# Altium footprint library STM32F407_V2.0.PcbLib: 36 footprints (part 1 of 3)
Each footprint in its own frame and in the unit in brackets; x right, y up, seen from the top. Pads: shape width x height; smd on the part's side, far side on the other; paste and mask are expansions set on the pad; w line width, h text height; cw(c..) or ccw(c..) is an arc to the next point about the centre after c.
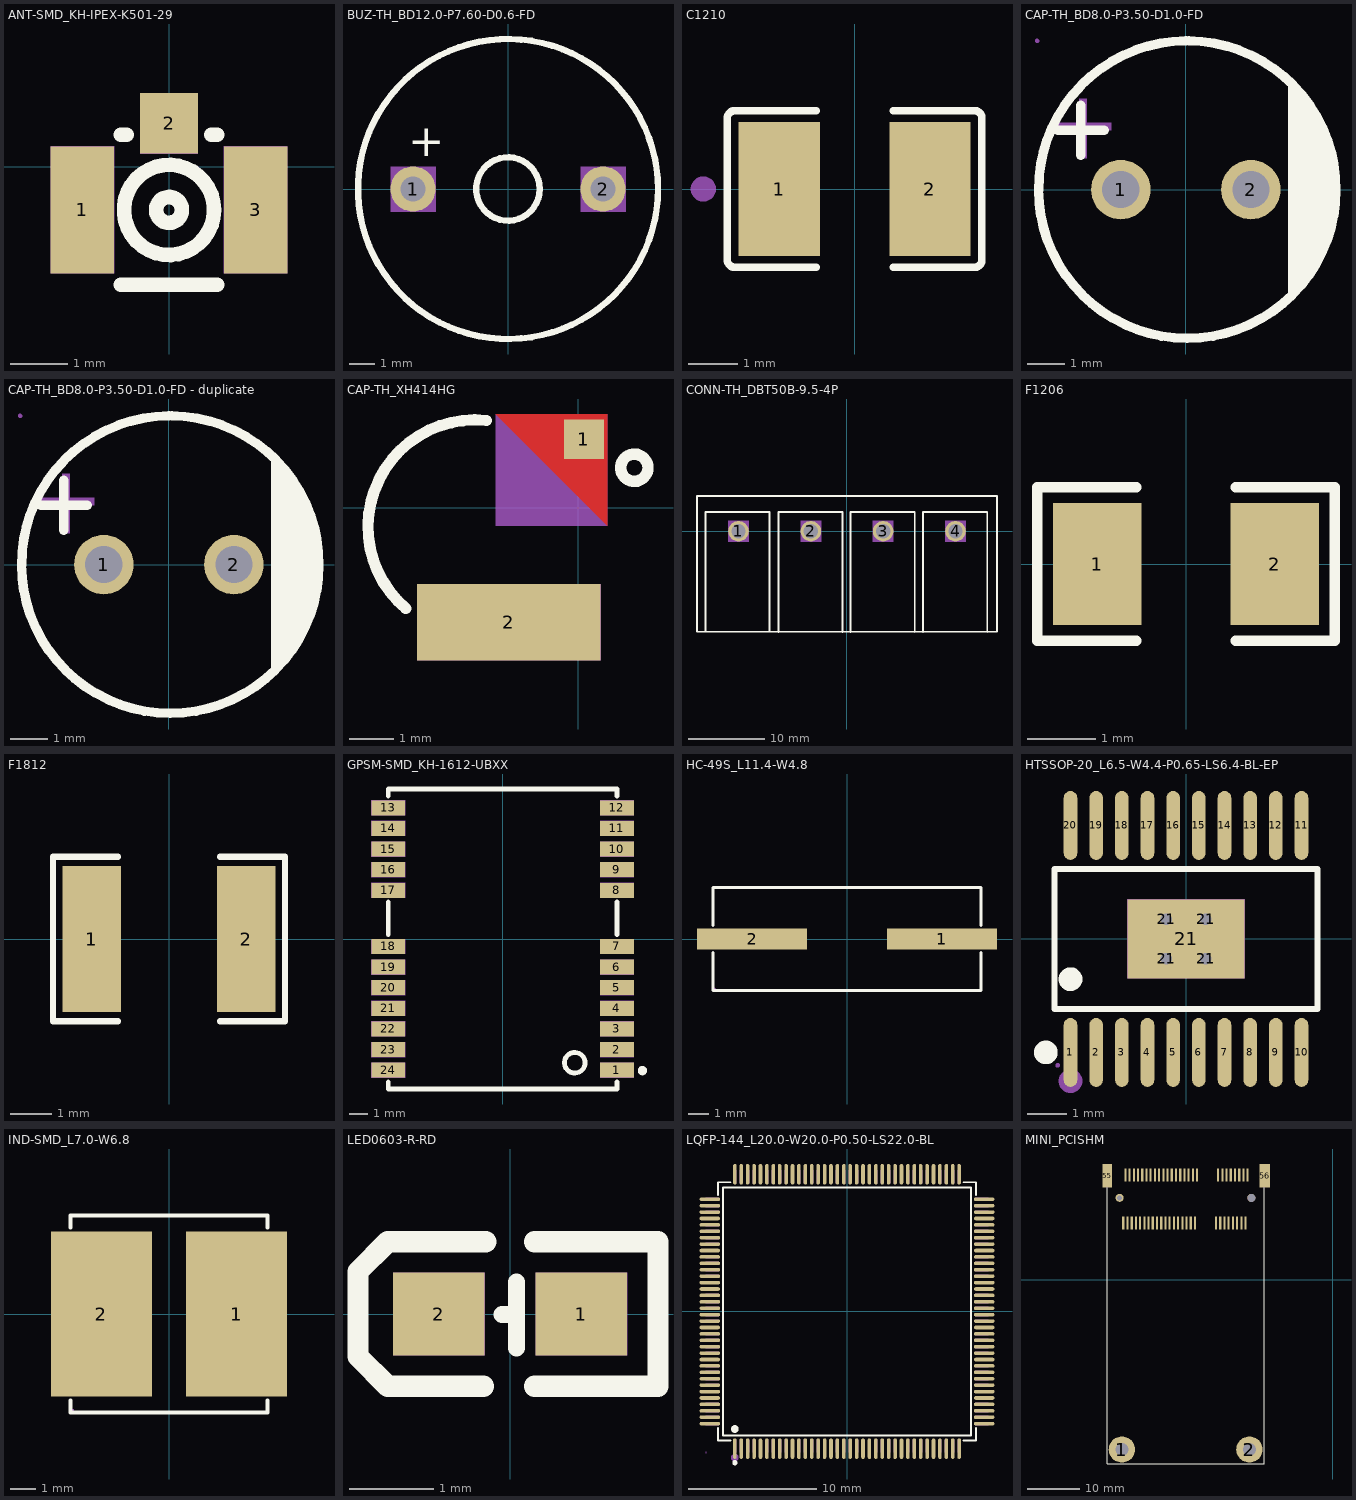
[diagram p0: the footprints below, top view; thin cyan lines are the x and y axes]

## ANT-SMD_KH-IPEX-K501-29 [mm]
pads (3):
  rect 1.1x2.2 smd: 1(-1.5,-0.75) 3(1.5,-0.75)
  rect 1x1.05 smd: 2(0,0.75)
Top Overlay:
  circle w0.254: c0,-0.75 r0.224
  circle w0.254: c0,-0.75 r0.781
  lines w0.254: -0.837,-2.05 0.837,-2.05 ; -0.837,0.55 -0.731,0.55 ; 0.731,0.55 0.837,0.55
Mechanical 5:
  region: 0.95,0.35 2.05,0.35 2.05,-1.85 0.95,-1.85
  region: -0.5,1.275 0.5,1.275 0.5,0.225 -0.5,0.225
  region: -2.05,0.35 -0.95,0.35 -0.95,-1.85 -2.05,-1.85

## BUZ-TH_BD12.0-P7.60-D0.6-FD [mm]
pads (2):
  round 1.8 hole 1: 1(-3.8,0) 2(3.8,0)
Top Overlay:
  circle w0.254: c0,0 r1.27
  circle w0.254: c0,0 r6
  text "+" at -3.996,1.316 h1.27
Mechanical 5:
  region: 2.9,0.9 4.7,0.9 4.7,-0.9 2.9,-0.9
  region: -4.7,0.9 -2.9,0.9 -2.9,-0.9 -4.7,-0.9

## C1210 [mm]
pads (2):
  rect 1.635x2.7 smd: 1(-1.517,0) 2(1.517,0)
Top Overlay:
  lines w0.152: -0.776,-1.579 -2.411,-1.579 cw(c-2.411,-1.426) -2.564,-1.426 -2.564,1.426 cw(c-2.411,1.426) -2.411,1.579 -0.776,1.579 ; 0.776,-1.579 2.411,-1.579 ccw(c2.411,-1.426) 2.564,-1.426 2.564,1.426 ccw(c2.411,1.426) 2.411,1.579 0.776,1.579
Top Paste:
  region: 0.7,-1.25 0.7,-0.559 0.8,-0.459 1.156,-0.459 1.256,-0.359 1.256,0.359 1.156,0.459 0.8,0.459 0.7,0.559 0.7,1.25 0.8,1.35 2.235,1.35 2.335,1.25 2.335,-1.25 2.235,-1.35 0.8,-1.35
  region: -0.7,-1.25 -0.7,-0.559 -0.8,-0.459 -1.156,-0.459 -1.256,-0.359 -1.256,0.359 -1.156,0.459 -0.8,0.459 -0.7,0.559 -0.7,1.25 -0.8,1.35 -2.235,1.35 -2.335,1.25 -2.335,-1.25 -2.235,-1.35 -0.8,-1.35
Mechanical 5:
  region: -1.6,-1.25 -1.6,1.25 -1,1.25 -1,-1.25
  region: 1.6,-1.25 1.6,1.25 1,1.25 1,-1.25
Mechanical 6:
  circle w0.06: c-1.6,-1.25 r0.03
Mechanical 15:
  circle w0.254: c-3.048,0 r0.127

## CAP-TH_BD8.0-P3.50-D1.0-FD [mm]
pads (2):
  round 1.6 hole 1: 1(-1.75,0) 2(1.75,0)
Top Overlay:
  region: 2.75,-3 2.941,-2.8 3.268,-2.355 3.536,-1.872 3.741,-1.359 3.88,-0.824 3.95,-0.276 3.95,0.276 3.88,0.824 3.741,1.359 3.536,1.872 3.268,2.355 2.941,2.8 2.75,3
  lines w0.254: -3.445,1.6 -2.2,1.6 ; -2.822,0.927 -2.822,2.273 ; 0.003,4 ccw(c0.038,0.001) 0.074,4
Mechanical 5:
  circle w0.3: c-1.75,0 r0.15
  circle w0.3: c1.75,0 r0.15
Mechanical 6:
  circle w0.06: c-4,4 r0.03
Mechanical 15:
  region: -2.865,0.845 -2.865,2.445 -2.665,2.445 -2.665,0.845
  region: -3.6,1.8 -2,1.8 -2,1.6 -3.6,1.6

## CAP-TH_BD8.0-P3.50-D1.0-FD - duplicate [mm]
pads (2):
  round 1.6 hole 1: 1(-1.75,0) 2(1.75,0)
Top Overlay:
  region: 2.75,-3 2.941,-2.8 3.268,-2.355 3.536,-1.872 3.741,-1.359 3.88,-0.824 3.95,-0.276 3.95,0.276 3.88,0.824 3.741,1.359 3.536,1.872 3.268,2.355 2.941,2.8 2.75,3
  lines w0.254: -3.445,1.6 -2.2,1.6 ; -2.822,0.927 -2.822,2.273 ; 0.003,4 ccw(c0.038,0.001) 0.074,4
Mechanical 5:
  circle w0.3: c-1.75,0 r0.15
  circle w0.3: c1.75,0 r0.15
Mechanical 6:
  circle w0.06: c-4,4 r0.03
Mechanical 15:
  region: -2.865,0.845 -2.865,2.445 -2.665,2.445 -2.665,0.845
  region: -3.6,1.8 -2,1.8 -2,1.6 -3.6,1.6

## CAP-TH_XH414HG [mil]
pads (3):
  round 0 smd: 1(-23.48,57.63)
  rect 35x35 smd: 1(5,60)
  rect 161.4x66.93 smd: 2(-60.88,-100.83)
Top Layer:
  region: -72.69,82.24 25.74,82.24 25.74,-16.19
Top Overlay:
  circle w10: c49.36,34.99 r12
  lines w10: -151.56,-88.79 cw(c-90.63,-17.05) -80.7,76.56
Top Paste:
  region: -72.69,82.24 25.74,82.24 25.74,-16.19
Top Solder:
  region: -72.69,82.24 25.74,82.24 25.74,-16.19
Mechanical 5:
  region: -72.69,82.24 25.74,82.24 25.74,-16.19 -72.69,-16.19
  region: -141.58,-67.37 19.82,-67.37 19.82,-134.3 -141.58,-134.3
Mechanical 15:
  lines w0.1: -62.82,-8.75 -60.82,-6.75

## CONN-TH_DBT50B-9.5-4P [mm]
pads (4):
  round 2.7 hole 1.9: 1(-14.25,0) 2(-4.75,0) 3(4.75,0) 4(14.25,0)
Top Overlay:
  lines w0.254: -18.595,-13.2 -18.595,2.54 -10.159,2.54 -10.159,-13.2 ; -9.016,-13.208 -9.016,2.532 -0.58,2.532 -0.58,-13.208 ; 0.458,-13.208 0.458,2.532 8.894,2.532 8.894,-13.208 ; 9.983,-13.208 9.983,2.532 18.419,2.532 18.419,-13.208 ; -19.7,-13.2 19.7,-13.2 19.7,4.6 -19.7,4.6 -19.7,-13.2
Mechanical 5:
  region: 12.9,1.35 15.6,1.35 15.6,-1.35 12.9,-1.35
  region: 3.4,1.35 6.1,1.35 6.1,-1.35 3.4,-1.35
  region: -6.1,1.35 -3.4,1.35 -3.4,-1.35 -6.1,-1.35
  region: -15.6,1.35 -12.9,1.35 -12.9,-1.35 -15.6,-1.35

## F1206 [mm]
pads (2):
  rect 1.293x1.782 smd: 1(-1.296,0) 2(1.296,0)
Top Overlay:
  lines w0.152: -0.726,-1.12 -2.172,-1.12 -2.172,1.12 -0.726,1.12 ; 0.726,-1.12 2.172,-1.12 2.172,1.12 0.726,1.12
Top Paste:
  region: -0.65,-0.791 -0.65,-0.403 -0.75,-0.303 -0.99,-0.303 -1.09,-0.203 -1.09,0.203 -0.99,0.303 -0.75,0.303 -0.65,0.403 -0.65,0.791 -0.75,0.891 -1.843,0.891 -1.943,0.791 -1.943,-0.791 -1.843,-0.891 -0.75,-0.891
  region: 0.65,-0.791 0.65,-0.403 0.75,-0.303 0.99,-0.303 1.09,-0.203 1.09,0.203 0.99,0.303 0.75,0.303 0.65,0.403 0.65,0.791 0.75,0.891 1.843,0.891 1.943,0.791 1.943,-0.791 1.843,-0.891 0.75,-0.891
Mechanical 5:
  region: 1.625,-0.825 1.625,0.825 0.975,0.825 0.975,-0.825
  region: -1.625,-0.825 -1.625,0.825 -0.975,0.825 -0.975,-0.825
Mechanical 6:
  circle w0.06: c-1.625,-0.825 r0.03

## F1812 [mm]
pads (2):
  rect 1.407x3.499 smd: 1(-1.853,0) 2(1.853,0)
Top Overlay:
  lines w0.152: -1.226,-1.978 -2.785,-1.978 -2.785,1.978 -1.226,1.978 ; 1.226,-1.978 2.785,-1.978 2.785,1.978 1.226,1.978
Top Paste:
  region: -1.15,-1.65 -1.15,-0.695 -1.25,-0.595 -1.528,-0.595 -1.628,-0.495 -1.628,0.495 -1.528,0.595 -1.25,0.595 -1.15,0.695 -1.15,1.65 -1.25,1.75 -2.457,1.75 -2.557,1.65 -2.557,-1.65 -2.457,-1.75 -1.25,-1.75
  region: 1.15,-1.65 1.15,-0.695 1.25,-0.595 1.528,-0.595 1.628,-0.495 1.628,0.495 1.528,0.595 1.25,0.595 1.15,0.695 1.15,1.65 1.25,1.75 2.457,1.75 2.557,1.65 2.557,-1.65 2.457,-1.75 1.25,-1.75
Mechanical 5:
  region: 2.275,-1.62 2.275,1.62 1.525,1.62 1.525,-1.62
  region: -2.275,-1.62 -2.275,1.62 -1.525,1.62 -1.525,-1.62
Mechanical 6:
  circle w0.06: c-2.275,-1.62 r0.03

## GPSM-SMD_KH-1612-UBXX [mm]
pads (24):
  rect 1.8x0.8 smd: 1(6.1,-7) 2(6.1,-5.9) 3(6.1,-4.8) 4(6.1,-3.7) 5(6.1,-2.6) 6(6.1,-1.5) 7(6.1,-0.4) 8(6.1,2.6) 9(6.1,3.7) 10(6.1,4.8) 11(6.1,5.9) 12(6.1,7) 13(-6.1,7) 14(-6.1,5.9) 15(-6.1,4.8) 16(-6.1,3.7) 17(-6.1,2.6) 18(-6.1,-0.4) 19(-6.1,-1.5) 20(-6.1,-2.6) 21(-6.1,-3.7) 22(-6.1,-4.8) 23(-6.1,-5.9) 24(-6.1,-7)
Top Overlay:
  circle w0.254: c3.85,-6.6 r0.55
  circle w0.254: c7.46,-7.02 r0.12
  lines w0.254: -6.1,-7.631 -6.1,-8 6.1,-8 6.1,-7.631 ; -6.1,0.231 -6.1,1.969 ; -6.1,7.631 -6.1,8 6.1,8 6.1,7.631 ; 6.1,0.231 6.1,1.969
Mechanical 5:
  region: 5.2,-6.6 7,-6.6 7,-7.4 5.2,-7.4
  region: 5.2,-5.5 7,-5.5 7,-6.3 5.2,-6.3
  region: 5.2,-4.4 7,-4.4 7,-5.2 5.2,-5.2
  region: 5.2,-3.3 7,-3.3 7,-4.1 5.2,-4.1
  region: 5.2,-2.2 7,-2.2 7,-3 5.2,-3
  region: 5.2,-1.1 7,-1.1 7,-1.9 5.2,-1.9
  region: 5.2,0 7,0 7,-0.8 5.2,-0.8
  region: 5.2,3 7,3 7,2.2 5.2,2.2
  region: 5.2,4.1 7,4.1 7,3.3 5.2,3.3
  region: 5.2,5.2 7,5.2 7,4.4 5.2,4.4
  region: 5.2,6.3 7,6.3 7,5.5 5.2,5.5
  region: 5.2,7.4 7,7.4 7,6.6 5.2,6.6
  region: -7,7.4 -5.2,7.4 -5.2,6.6 -7,6.6
  region: -7,6.3 -5.2,6.3 -5.2,5.5 -7,5.5
  region: -7,5.2 -5.2,5.2 -5.2,4.4 -7,4.4
  region: -7,4.1 -5.2,4.1 -5.2,3.3 -7,3.3
  region: -7,3 -5.2,3 -5.2,2.2 -7,2.2
  region: -7,0 -5.2,0 -5.2,-0.8 -7,-0.8
  region: -7,-1.1 -5.2,-1.1 -5.2,-1.9 -7,-1.9
  region: -7,-2.2 -5.2,-2.2 -5.2,-3 -7,-3
  region: -7,-3.3 -5.2,-3.3 -5.2,-4.1 -7,-4.1
  region: -7,-4.4 -5.2,-4.4 -5.2,-5.2 -7,-5.2
  region: -7,-5.5 -5.2,-5.5 -5.2,-6.3 -7,-6.3
  region: -7,-6.6 -5.2,-6.6 -5.2,-7.4 -7,-7.4

## HC-49S_L11.4-W4.8 [mm] "晶振8M"
pads (2):
  rect 5.274x1.02 smd: 1(4.553,0) 2(-4.553,0)
Top Overlay:
  lines w0.152: -6.426,-0.662 -6.426,-2.476 6.426,-2.476 6.426,-0.662 ; -6.426,0.662 -6.426,2.476 6.426,2.476 6.426,0.662
Mechanical 5:
  region: 6.35,-0.3 6.35,0.3 2,0.3 2,-0.3
  region: -6.35,-0.3 -6.35,0.3 -2,0.3 -2,-0.3
Mechanical 6:
  circle w0.06: c-6.35,-2.4 r0.03

## HTSSOP-20_L6.5-W4.4-P0.65-LS6.4-BL-EP [mm]
pads (25):
  oval 0.343x1.747 smd: 1(-2.925,-2.873) 2(-2.275,-2.873) 3(-1.625,-2.873) 4(-0.975,-2.873) 5(-0.325,-2.873) 6(0.325,-2.873) 7(0.975,-2.873) 8(1.625,-2.873) 9(2.275,-2.873) 10(2.925,-2.873) 11(2.925,2.873) 12(2.275,2.873) 13(1.625,2.873) 14(0.975,2.873) 15(0.325,2.873) 16(-0.325,2.873) 17(-0.975,2.873) 18(-1.625,2.873) 19(-2.275,2.873) 20(-2.925,2.873)
  round 0.6 hole 0.3: 21(-0.5,-0.5) 21(-0.5,0.5) 21(0.5,-0.5) 21(0.5,0.5)
  rect 2.975x2 smd: 21(0,0)
Top Overlay:
  circle w0.3: c-3.549,-2.873 r0.15
  circle w0.3: c-2.925,-1.019 r0.15
  lines w0.152: -3.326,-1.771 3.326,-1.771 3.326,1.771 -3.326,1.771 -3.326,-1.771
Mechanical 5:
  drawing of 41 lines, arcs and shapes, not listed
Mechanical 6:
  circle w0.06: c-3.25,-3.2 r0.03
Mechanical 15:
  circle w0.3: c-2.925,-3.6 r0.15

## IND-SMD_L7.0-W6.8 [mm]
pads (2):
  rect 3.924x6.42 smd: 1(2.628,0) 2(-2.628,0)
Top Overlay:
  lines w0.152: -3.826,-3.362 -3.826,-3.826 3.826,-3.826 3.826,-3.362 ; -3.826,3.362 -3.826,3.826 3.826,3.826 3.826,3.362
Mechanical 5:
  region: 3.75,-3 3.75,3 0.75,3 0.75,-3
  region: -3.75,-3 -3.75,3 -0.75,3 -0.75,-3
Mechanical 6:
  circle w0.06: c-3.75,-3.75 r0.03

## LED0603-R-RD [mil]
pads (2):
  rect 43x39 smd: 1(33.5,0) 2(-33.5,0)
Top Overlay:
  lines w7.99: -3.9,-0.31 3,-0.31 ; 3,-16 3,15
  lines w10: -12.5,-34 -57.5,-34 -71.5,-20 -71.5,20 -57.5,34 -11.5,34 ; 11.5,-34 69.5,-34 69.5,34 11.5,34
Mechanical 5:
  region: -55,19.5 -12,19.5 -12,-19.5 -55,-19.5
  region: 12,19.5 55,19.5 55,-19.5 12,-19.5

## LQFP-144_L20.0-W20.0-P0.50-LS22.0-BL [mm] "MCU"
pads (144):
  oval 0.28x1.6 smd: 1(-8.75,-10.7) 2(-8.25,-10.7) 3(-7.75,-10.7) 4(-7.25,-10.7) 5(-6.75,-10.7) 6(-6.25,-10.7) 7(-5.75,-10.7) 8(-5.25,-10.7) 9(-4.75,-10.7) 10(-4.25,-10.7) 11(-3.75,-10.7) 12(-3.25,-10.7) 13(-2.75,-10.7) 14(-2.25,-10.7) 15(-1.75,-10.7) 16(-1.25,-10.7) 17(-0.75,-10.7) 18(-0.25,-10.7) 19(0.25,-10.7) 20(0.75,-10.7) 21(1.25,-10.7) 22(1.75,-10.7) 23(2.25,-10.7) 24(2.75,-10.7) 25(3.25,-10.7) 26(3.75,-10.7) 27(4.25,-10.7) 28(4.75,-10.7) 29(5.25,-10.7) 30(5.75,-10.7) 31(6.25,-10.7) 32(6.75,-10.7) 33(7.25,-10.7) 34(7.75,-10.7) 35(8.25,-10.7) 36(8.75,-10.7) 73(8.75,10.7) 74(8.25,10.7) 75(7.75,10.7) 76(7.25,10.7) 77(6.75,10.7) 78(6.25,10.7) 79(5.75,10.7) 80(5.25,10.7) 81(4.75,10.7) 82(4.25,10.7) 83(3.75,10.7) 84(3.25,10.7) 85(2.75,10.7) 86(2.25,10.7) 87(1.75,10.7) 88(1.25,10.7) 89(0.75,10.7) 90(0.25,10.7) 91(-0.25,10.7) 92(-0.75,10.7) 93(-1.25,10.7) 94(-1.75,10.7) 95(-2.25,10.7) 96(-2.75,10.7) 97(-3.25,10.7) 98(-3.75,10.7) 99(-4.25,10.7) 100(-4.75,10.7) 101(-5.25,10.7) 102(-5.75,10.7) 103(-6.25,10.7) 104(-6.75,10.7) 105(-7.25,10.7) 106(-7.75,10.7) 107(-8.25,10.7) 108(-8.75,10.7)
  oval 1.6x0.28 smd: 37(10.7,-8.75) 38(10.7,-8.25) 39(10.7,-7.75) 40(10.7,-7.25) 41(10.7,-6.75) 42(10.7,-6.25) 43(10.7,-5.75) 44(10.7,-5.25) 45(10.7,-4.75) 46(10.7,-4.25) 47(10.7,-3.75) 48(10.7,-3.25) 49(10.7,-2.75) 50(10.7,-2.25) 51(10.7,-1.75) 52(10.7,-1.25) 53(10.7,-0.75) 54(10.7,-0.25) 55(10.7,0.25) 56(10.7,0.75) 57(10.7,1.25) 58(10.7,1.75) 59(10.7,2.25) 60(10.7,2.75) 61(10.7,3.25) 62(10.7,3.75) 63(10.7,4.25) 64(10.7,4.75) 65(10.7,5.25) 66(10.7,5.75) 67(10.7,6.25) 68(10.7,6.75) 69(10.7,7.25) 70(10.7,7.75) 71(10.7,8.25) 72(10.7,8.75) 109(-10.7,8.75) 110(-10.7,8.25) 111(-10.7,7.75) 112(-10.7,7.25) 113(-10.7,6.75) 114(-10.7,6.25) 115(-10.7,5.75) 116(-10.7,5.25) 117(-10.7,4.75) 118(-10.7,4.25) 119(-10.7,3.75) 120(-10.7,3.25) 121(-10.7,2.75) 122(-10.7,2.25) 123(-10.7,1.75) 124(-10.7,1.25) 125(-10.7,0.75) 126(-10.7,0.25) 127(-10.7,-0.25) 128(-10.7,-0.75) 129(-10.7,-1.25) 130(-10.7,-1.75) 131(-10.7,-2.25) 132(-10.7,-2.75) 133(-10.7,-3.25) 134(-10.7,-3.75) 135(-10.7,-4.25) 136(-10.7,-4.75) 137(-10.7,-5.25) 138(-10.7,-5.75) 139(-10.7,-6.25) 140(-10.7,-6.75) 141(-10.7,-7.25) 142(-10.7,-7.75) 143(-10.7,-8.25) 144(-10.7,-8.75)
Top Overlay:
  circle w0.2: c-8.75,-11.8 r0.1
  circle w0.3: c-8.75,-9.171 r0.15
  lines w0.152: -10.076,-9.08 -10.076,-10.076 -9.08,-10.076 ; -10.076,9.08 -10.076,10.076 -9.08,10.076 ; 9.08,-10.076 10.076,-10.076 10.076,-9.08 ; 9.08,10.076 10.076,10.076 10.076,9.08 ; -9.671,-9.671 9.671,-9.671 9.671,9.671 -9.671,9.671 -9.671,-9.671
Mechanical 5:
  drawing of 288 lines, arcs and shapes, not listed
Mechanical 6:
  circle w0.06: c-11,-11 r0.03
Mechanical 15:
  circle w0.3: c-8.75,-11.4 r0.15

## MINI_PCISHM [mm]
pads (58):
  round 5 hole 2.5: 1(-40.01,-32.221) 2(-15.81,-32.221)
  rect 0.4x2.5 smd: 1(-16.14,19.879) 2(-16.54,10.779) 3(-16.94,19.879) 4(-17.34,10.779) 5(-17.74,19.879) 6(-18.14,10.779) 7(-18.54,19.879) 8(-18.94,10.779) 9(-19.34,19.879) 10(-19.74,10.779) 11(-20.14,19.879) 12(-20.54,10.779) 13(-20.94,19.879) 14(-21.34,10.779) 15(-21.74,19.879) 16(-22.14,10.779) 17(-25.74,19.879) 18(-26.14,10.779) 19(-26.54,19.879) 20(-26.94,10.779) 21(-27.34,19.879) 22(-27.74,10.779) 23(-28.14,19.879) 24(-28.54,10.779) 25(-28.94,19.879) 26(-29.34,10.779) 27(-29.74,19.879) 28(-30.14,10.779) 29(-30.54,19.879) 30(-30.94,10.779) 31(-31.34,19.879) 32(-31.74,10.779) 33(-32.14,19.879) 34(-32.54,10.779) 35(-32.94,19.879) 36(-33.34,10.779) 37(-33.74,19.879) 38(-34.14,10.779) 39(-34.54,19.879) 40(-34.94,10.779) 41(-35.34,19.879) 42(-35.74,10.779) 43(-36.14,19.879) 44(-36.54,10.779) 45(-36.94,19.879) 46(-37.34,10.779) 47(-37.74,19.879) 48(-38.14,10.779) 49(-38.54,19.879) 50(-38.94,10.779) 51(-39.34,19.879) 52(-39.74,10.779)
  rect 1.8x4.5 smd: 55(-42.74,19.704)
  rect 2x4.5 smd: 56(-12.94,19.704)
  round 1.524 hole 0.991: 57(-40.44,15.529)
  round 1.5 hole 1.5: 58(-15.44,15.529)
Top Overlay:
  lines w0.2: -42.81,18.939 -42.81,-34.971 -13.01,-34.971 -13.01,18.939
